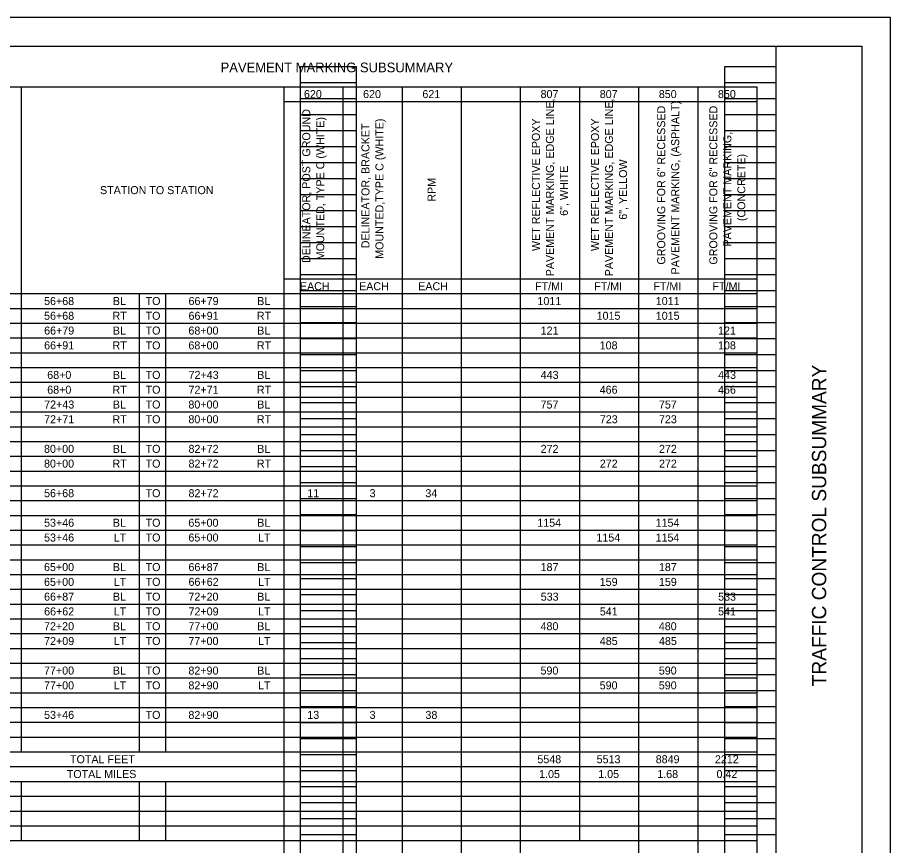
# Model space of a CAD drawing. Extents: x -6.8 to 34, y 0 to 22.
# Drawn here: x 18.73 to 34, y 7.51 to 22 of the extents above; entities that cross this region are included whole.
import ezdxf

# ---------------------------------------------------------------- set-up
doc = ezdxf.new("R2010")
doc.units = 0
for name, color, linetype in [('SH_Border', 7, 'Continuous'), ('SH_Cut_Line', 7, 'Continuous'), ('SH_Data', 7, 'Continuous'), ('SH_Text', 7, 'Continuous')]:
    doc.layers.add(name, color=color, linetype=linetype)

msp = doc.modelspace()

# ---------------------------------------------------------------- linework, layer by layer
at = {"layer": 'SH_Border'}
msp.add_line((32, 0.5), (32, 21.5), dxfattribs=at)
msp.add_lwpolyline([(1.5, 21.5), (33.5, 21.5), (33.5, 0.5), (1.5, 0.5)], close=True, dxfattribs=at)
at = {"layer": 'SH_Cut_Line'}
msp.add_lwpolyline([(0, 0), (34, 0), (34, 22), (0, 22)], close=True, dxfattribs=at)
at = {"layer": 'SH_Data'}
for p, q in [((23.68, 0.98), (23.68, 21.14)), ((23.68, 21.14), (24.66, 21.14)), ((24.66, 0.98), (24.66, 21.14)), ((31.1, 0.98), (31.1, 21.14)), ((31.1, 21.14), (32, 21.14)), ((32, 0.98), (32, 21.14)), ((23.68, 20.86), (24.66, 20.86)), ((31.1, 20.86), (32, 20.86)), ((23.68, 20.58), (24.66, 20.58)), ((31.1, 20.58), (32, 20.58)), ((23.68, 20.3), (24.66, 20.3)), ((31.1, 20.3), (32, 20.3)), ((23.68, 20.02), (24.66, 20.02)), ((31.1, 20.02), (32, 20.02)), ((23.68, 19.74), (24.66, 19.74)), ((31.1, 19.74), (32, 19.74)), ((23.68, 19.46), (24.66, 19.46)), ((31.1, 19.46), (32, 19.46)), ((23.68, 19.18), (24.66, 19.18)), ((31.1, 19.18), (32, 19.18)), ((23.68, 18.9), (24.66, 18.9)), ((31.1, 18.9), (32, 18.9)), ((23.68, 18.62), (24.66, 18.62)), ((31.1, 18.62), (32, 18.62)), ((23.68, 18.34), (24.66, 18.34)), ((31.1, 18.34), (32, 18.34)), ((23.68, 18.06), (24.66, 18.06)), ((31.1, 18.06), (32, 18.06)), ((23.68, 17.78), (24.66, 17.78)), ((31.1, 17.78), (32, 17.78)), ((23.68, 17.5), (24.66, 17.5)), ((31.1, 17.5), (32, 17.5)), ((23.68, 17.22), (24.66, 17.22)), ((31.1, 17.22), (32, 17.22)), ((23.68, 16.94), (24.66, 16.94)), ((31.1, 16.94), (32, 16.94)), ((23.68, 16.66), (24.66, 16.66)), ((31.1, 16.66), (32, 16.66)), ((23.68, 16.38), (24.66, 16.38)), ((31.1, 16.38), (32, 16.38)), ((23.68, 16.1), (24.66, 16.1)), ((31.1, 16.1), (32, 16.1)), ((23.68, 15.82), (24.66, 15.82)), ((31.1, 15.82), (32, 15.82)), ((23.68, 15.54), (24.66, 15.54)), ((31.1, 15.54), (32, 15.54)), ((23.68, 15.26), (24.66, 15.26)), ((31.1, 15.26), (32, 15.26)), ((23.68, 14.98), (24.66, 14.98)), ((31.1, 14.98), (32, 14.98)), ((23.68, 14.7), (24.66, 14.7)), ((31.1, 14.7), (32, 14.7)), ((23.68, 14.42), (24.66, 14.42)), ((31.1, 14.42), (32, 14.42)), ((23.68, 14.14), (24.66, 14.14)), ((31.1, 14.14), (32, 14.14)), ((23.68, 13.86), (24.66, 13.86)), ((31.1, 13.86), (32, 13.86)), ((23.68, 13.58), (24.66, 13.58)), ((31.1, 13.58), (32, 13.58)), ((23.68, 13.3), (24.66, 13.3)), ((31.1, 13.3), (32, 13.3)), ((23.68, 13.02), (24.66, 13.02)), ((31.1, 13.02), (32, 13.02)), ((23.68, 12.74), (24.66, 12.74)), ((31.1, 12.74), (32, 12.74)), ((23.68, 12.46), (24.66, 12.46)), ((31.1, 12.46), (32, 12.46)), ((23.68, 12.18), (24.66, 12.18)), ((31.1, 12.18), (32, 12.18)), ((23.68, 11.9), (24.66, 11.9)), ((31.1, 11.9), (32, 11.9)), ((23.68, 11.62), (24.66, 11.62)), ((31.1, 11.62), (32, 11.62)), ((23.68, 11.34), (24.66, 11.34)), ((31.1, 11.34), (32, 11.34)), ((23.68, 11.06), (24.66, 11.06)), ((31.1, 11.06), (32, 11.06)), ((23.68, 10.78), (24.66, 10.78)), ((31.1, 10.78), (32, 10.78)), ((23.68, 10.5), (24.66, 10.5)), ((31.1, 10.5), (32, 10.5)), ((23.68, 10.22), (24.66, 10.22)), ((31.1, 10.22), (32, 10.22)), ((23.68, 9.94), (24.66, 9.94)), ((31.1, 9.94), (32, 9.94)), ((23.68, 9.66), (24.66, 9.66)), ((31.1, 9.66), (32, 9.66)), ((23.68, 9.38), (24.66, 9.38)), ((31.1, 9.38), (32, 9.38)), ((23.68, 9.1), (24.66, 9.1)), ((31.1, 9.1), (32, 9.1)), ((23.68, 8.82), (24.66, 8.82)), ((31.1, 8.82), (32, 8.82)), ((23.68, 8.54), (24.66, 8.54)), ((31.1, 8.54), (32, 8.54)), ((23.68, 8.26), (24.66, 8.26)), ((31.1, 8.26), (32, 8.26)), ((23.68, 7.98), (24.66, 7.98)), ((31.1, 7.98), (32, 7.98)), ((23.68, 7.7), (24.66, 7.7)), ((31.1, 7.7), (32, 7.7))]:
    msp.add_line(p, q, dxfattribs=at)
at = {"layer": 'SH_Text'}
for p, q in [((16.932, 20.788), (31.662, 20.788)), ((18.789, 20.788), (18.789, 9.147)), ((23.384, 20.788), (23.384, 7.078)), ((24.419, 20.788), (24.419, 7.078)), ((25.454, 20.788), (25.454, 7.078)), ((26.489, 20.788), (26.489, 7.078)), ((27.523, 20.788), (27.523, 7.078)), ((28.558, 20.788), (28.558, 7.595)), ((29.593, 20.788), (29.593, 7.078)), ((30.628, 20.788), (30.628, 7.078)), ((31.662, 20.788), (31.662, 7.078)), ((23.384, 20.53), (31.662, 20.53)), ((23.384, 17.425), (31.662, 17.425)), ((16.932, 17.167), (31.662, 17.167)), ((20.858, 17.167), (20.858, 9.147)), ((21.315, 17.167), (21.315, 9.147)), ((16.932, 16.908), (31.662, 16.908)), ((16.932, 16.649), (31.662, 16.649)), ((16.932, 16.391), (31.662, 16.391)), ((16.932, 16.132), (31.662, 16.132)), ((16.932, 15.873), (31.662, 15.873)), ((16.932, 15.615), (31.662, 15.615)), ((16.932, 15.356), (31.662, 15.356)), ((16.932, 15.097), (31.662, 15.097)), ((16.932, 14.838), (31.662, 14.838)), ((16.932, 14.58), (31.662, 14.58)), ((16.932, 14.321), (31.662, 14.321)), ((16.932, 14.062), (31.662, 14.062)), ((16.932, 13.804), (31.662, 13.804)), ((16.932, 13.545), (31.662, 13.545)), ((16.932, 13.286), (31.662, 13.286)), ((16.932, 13.028), (31.662, 13.028)), ((16.932, 12.769), (31.662, 12.769)), ((16.932, 12.51), (31.662, 12.51)), ((16.932, 12.251), (31.662, 12.251)), ((16.932, 11.993), (31.662, 11.993)), ((16.932, 11.734), (31.662, 11.734)), ((16.932, 11.475), (31.662, 11.475)), ((16.932, 11.217), (31.662, 11.217)), ((16.932, 10.958), (31.662, 10.958)), ((16.932, 10.699), (31.662, 10.699)), ((16.932, 10.441), (31.662, 10.441)), ((16.932, 10.182), (31.662, 10.182)), ((16.932, 9.923), (31.662, 9.923)), ((16.932, 9.665), (31.662, 9.665)), ((16.932, 9.406), (31.662, 9.406)), ((16.932, 9.147), (31.662, 9.147)), ((16.932, 8.888), (31.662, 8.888)), ((16.932, 8.63), (31.662, 8.63)), ((18.789, 8.63), (18.789, 7.595)), ((20.858, 8.63), (20.858, 7.595)), ((21.315, 8.63), (21.315, 7.595)), ((16.932, 8.371), (31.662, 8.371)), ((16.932, 8.112), (31.662, 8.112)), ((16.932, 7.854), (31.662, 7.854)), ((16.932, 7.595), (31.662, 7.595))]:
    msp.add_line(p, q, dxfattribs=at)

# ---------------------------------------------------------------- texts
at = {"layer": 'SH_Data'}
msp.add_text('TRAFFIC CONTROL SUBSUMMARY', height=0.25, rotation=90, dxfattribs=at).set_placement((32.875, 10.295))
at = {"layer": 'SH_Text'}
for s, height, p in [('PAVEMENT MARKING SUBSUMMARY', 0.17, (22.28, 21.04)), ('620', 0.14, (23.738, 20.589)), ('620', 0.14, (24.773, 20.589)), ('621', 0.14, (25.81, 20.589)), ('807', 0.14, (27.878, 20.589)), ('807', 0.14, (28.913, 20.589)), ('850', 0.14, (29.946, 20.589)), ('850', 0.14, (30.981, 20.589)), ('STATION TO STATION', 0.14, (20.17, 18.908)), ('EACH', 0.14, (23.668, 17.226)), ('EACH', 0.14, (24.702, 17.226)), ('EACH', 0.14, (25.737, 17.226)), ('FT/MI', 0.14, (27.781, 17.226)), ('FT/MI', 0.14, (28.816, 17.226)), ('FT/MI', 0.14, (29.85, 17.226)), ('FT/MI', 0.14, (30.885, 17.226)), ('56+68', 0.14, (19.192, 16.967)), ('BL', 0.14, (20.395, 16.967)), ('TO', 0.14, (20.968, 16.967)), ('66+79', 0.14, (21.719, 16.967)), ('BL', 0.14, (22.921, 16.967)), ('1011', 0.14, (27.823, 16.967)), ('1011', 0.14, (29.893, 16.967)), ('56+68', 0.14, (19.192, 16.709)), ('RT', 0.14, (20.389, 16.709)), ('TO', 0.14, (20.968, 16.709)), ('66+91', 0.14, (21.719, 16.709)), ('RT', 0.14, (22.915, 16.709)), ('1015', 0.14, (28.858, 16.709)), ('1015', 0.14, (29.893, 16.709)), ('66+79', 0.14, (19.193, 16.45)), ('BL', 0.14, (20.395, 16.45)), ('TO', 0.14, (20.968, 16.45)), ('68+00', 0.14, (21.717, 16.45)), ('BL', 0.14, (22.921, 16.45)), ('121', 0.14, (27.879, 16.45)), ('121', 0.14, (30.983, 16.45)), ('66+91', 0.14, (19.193, 16.191)), ('RT', 0.14, (20.389, 16.191)), ('TO', 0.14, (20.968, 16.191)), ('68+00', 0.14, (21.717, 16.191)), ('RT', 0.14, (22.915, 16.191)), ('108', 0.14, (28.912, 16.191)), ('108', 0.14, (30.982, 16.191)), ('68+0', 0.14, (19.247, 15.674)), ('BL', 0.14, (20.395, 15.674)), ('TO', 0.14, (20.968, 15.674)), ('72+43', 0.14, (21.72, 15.674)), ('BL', 0.14, (22.921, 15.674)), ('443', 0.14, (27.88, 15.674)), ('443', 0.14, (30.984, 15.674)), ('68+0', 0.14, (19.247, 15.415)), ('RT', 0.14, (20.389, 15.415)), ('TO', 0.14, (20.968, 15.415)), ('72+71', 0.14, (21.719, 15.415)), ('RT', 0.14, (22.915, 15.415)), ('466', 0.14, (28.912, 15.415)), ('466', 0.14, (30.982, 15.415)), ('72+43', 0.14, (19.194, 15.156)), ('BL', 0.14, (20.395, 15.156)), ('TO', 0.14, (20.968, 15.156)), ('80+00', 0.14, (21.717, 15.156)), ('BL', 0.14, (22.921, 15.156)), ('757', 0.14, (27.878, 15.156)), ('757', 0.14, (29.948, 15.156)), ('72+71', 0.14, (19.193, 14.898)), ('RT', 0.14, (20.389, 14.898)), ('TO', 0.14, (20.968, 14.898)), ('80+00', 0.14, (21.717, 14.898)), ('RT', 0.14, (22.915, 14.898)), ('723', 0.14, (28.915, 14.898)), ('723', 0.14, (29.949, 14.898)), ('80+00', 0.14, (19.191, 14.38)), ('BL', 0.14, (20.395, 14.38)), ('TO', 0.14, (20.968, 14.38)), ('82+72', 0.14, (21.719, 14.38)), ('BL', 0.14, (22.921, 14.38)), ('272', 0.14, (27.879, 14.38)), ('272', 0.14, (29.949, 14.38)), ('80+00', 0.14, (19.191, 14.122)), ('RT', 0.14, (20.389, 14.122)), ('TO', 0.14, (20.968, 14.122)), ('82+72', 0.14, (21.719, 14.122)), ('RT', 0.14, (22.915, 14.122)), ('272', 0.14, (28.914, 14.122)), ('272', 0.14, (29.949, 14.122)), ('56+68', 0.14, (19.192, 13.604)), ('TO', 0.14, (20.968, 13.604)), ('82+72', 0.14, (21.719, 13.604)), ('3', 0.14, (24.887, 13.604)), ('34', 0.14, (25.863, 13.604)), ('11', 0.14, (23.796, 13.604)), ('53+46', 0.14, (19.192, 13.087)), ('BL', 0.14, (20.395, 13.087)), ('TO', 0.14, (20.968, 13.087)), ('65+00', 0.14, (21.717, 13.087)), ('BL', 0.14, (22.921, 13.087)), ('1154', 0.14, (27.82, 13.087)), ('1154', 0.14, (29.89, 13.087)), ('53+46', 0.14, (19.192, 12.828)), ('LT', 0.14, (20.409, 12.828)), ('TO', 0.14, (20.968, 12.828)), ('65+00', 0.14, (21.717, 12.828)), ('LT', 0.14, (22.935, 12.828)), ('1154', 0.14, (28.855, 12.828)), ('1154', 0.14, (29.89, 12.828)), ('65+00', 0.14, (19.191, 12.311)), ('BL', 0.14, (20.395, 12.311)), ('TO', 0.14, (20.968, 12.311)), ('66+87', 0.14, (21.718, 12.311)), ('BL', 0.14, (22.921, 12.311)), ('187', 0.14, (27.878, 12.311)), ('187', 0.14, (29.948, 12.311)), ('65+00', 0.14, (19.191, 12.052)), ('LT', 0.14, (20.409, 12.052)), ('TO', 0.14, (20.968, 12.052)), ('66+62', 0.14, (21.719, 12.052)), ('LT', 0.14, (22.935, 12.052)), ('159', 0.14, (28.913, 12.052)), ('159', 0.14, (29.948, 12.052)), ('66+87', 0.14, (19.192, 11.793)), ('BL', 0.14, (20.395, 11.793)), ('TO', 0.14, (20.968, 11.793)), ('72+20', 0.14, (21.717, 11.793)), ('BL', 0.14, (22.921, 11.793)), ('533', 0.14, (27.88, 11.793)), ('533', 0.14, (30.984, 11.793)), ('66+62', 0.14, (19.193, 11.535)), ('LT', 0.14, (20.409, 11.535)), ('TO', 0.14, (20.968, 11.535)), ('72+09', 0.14, (21.719, 11.535)), ('LT', 0.14, (22.935, 11.535)), ('541', 0.14, (28.914, 11.535)), ('541', 0.14, (30.983, 11.535)), ('72+20', 0.14, (19.191, 11.276)), ('BL', 0.14, (20.395, 11.276)), ('TO', 0.14, (20.968, 11.276)), ('77+00', 0.14, (21.717, 11.276)), ('BL', 0.14, (22.921, 11.276)), ('480', 0.14, (27.877, 11.276)), ('480', 0.14, (29.946, 11.276)), ('72+09', 0.14, (19.193, 11.017)), ('LT', 0.14, (20.409, 11.017)), ('TO', 0.14, (20.968, 11.017)), ('77+00', 0.14, (21.717, 11.017)), ('LT', 0.14, (22.935, 11.017)), ('485', 0.14, (28.914, 11.017)), ('485', 0.14, (29.949, 11.017)), ('77+00', 0.14, (19.191, 10.5)), ('BL', 0.14, (20.395, 10.5)), ('TO', 0.14, (20.968, 10.5)), ('82+90', 0.14, (21.717, 10.5)), ('BL', 0.14, (22.921, 10.5)), ('590', 0.14, (27.877, 10.5)), ('590', 0.14, (29.946, 10.5)), ('77+00', 0.14, (19.191, 10.241)), ('LT', 0.14, (20.409, 10.241)), ('TO', 0.14, (20.968, 10.241)), ('82+90', 0.14, (21.717, 10.241)), ('LT', 0.14, (22.935, 10.241)), ('590', 0.14, (28.912, 10.241)), ('590', 0.14, (29.946, 10.241)), ('53+46', 0.14, (19.192, 9.724)), ('TO', 0.14, (20.968, 9.724)), ('82+90', 0.14, (21.717, 9.724)), ('13', 0.14, (23.797, 9.724)), ('3', 0.14, (24.887, 9.724)), ('38', 0.14, (25.864, 9.724)), ('TOTAL FEET', 0.14, (19.646, 8.948)), ('5548', 0.14, (27.822, 8.948)), ('5513', 0.14, (28.859, 8.948)), ('8849', 0.14, (29.892, 8.948)), ('2212', 0.14, (30.928, 8.948)), ('TOTAL MILES', 0.14, (19.589, 8.689)), ('1.05', 0.14, (27.852, 8.689)), ('1.05', 0.14, (28.886, 8.689)), ('1.68', 0.14, (29.919, 8.689)), ('0.42', 0.14, (30.956, 8.689))]:
    msp.add_text(s, height=height, dxfattribs=at).set_placement(p)
for s, p in [('PAVEMENT MARKING, EDGE LINE, ', (28.111, 17.47)), ('PAVEMENT MARKING, EDGE LINE, ', (29.145, 17.47)), ('PAVEMENT MARKING, (ASPHALT)', (30.303, 17.503)), ('DELINEATOR, POST GROUND ', (23.849, 17.702)), ('GROOVING FOR 6" RECESSED ', (30.058, 17.674)), ('GROOVING FOR 6" RECESSED ', (30.97, 17.674)), ('MOUNTED, TYPE C (WHITE)', (24.094, 17.751)), ('MOUNTED,TYPE C (WHITE)', (25.129, 17.776)), ('WET REFLECTIVE EPOXY ', (27.866, 17.912)), ('WET REFLECTIVE EPOXY ', (28.9, 17.912)), ('DELINEATOR, BRACKET ', (24.884, 17.961)), ('PAVEMENT MARKING, ', (31.215, 17.991)), ('(CONCRETE)', (31.46, 18.436)), ('6", WHITE', (28.356, 18.529)), ('6", YELLOW', (29.39, 18.461)), ('RPM', (26.041, 18.776))]:
    msp.add_text(s, height=0.14, rotation=90, dxfattribs=at).set_placement(p)

doc.saveas('drawing.dxf')
